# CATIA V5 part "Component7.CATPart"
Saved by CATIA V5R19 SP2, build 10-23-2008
Part number: Component7
Definition: Component7
Nomenclature: Component7
Source: Unknown
Bounding box of the stored display mesh (mm): x -4.283 to 0.4, y 0 to 2.367, z 0 to 3.3
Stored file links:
  Z:\fausse table rondelle-20220905T211342Z-001\fausse table rondelle\Component7.CATPart
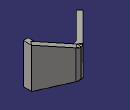
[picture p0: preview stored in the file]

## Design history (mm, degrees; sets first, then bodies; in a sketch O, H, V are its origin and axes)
AxisSystem1: origin (0, 0, 0), X (1, 0, 0), Y (0, 1, 0), Z (0, 0, 1)
Body1 "Body1" (main body)
  Solid1: solid without history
